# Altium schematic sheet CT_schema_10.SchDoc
size 390 x 385 mm
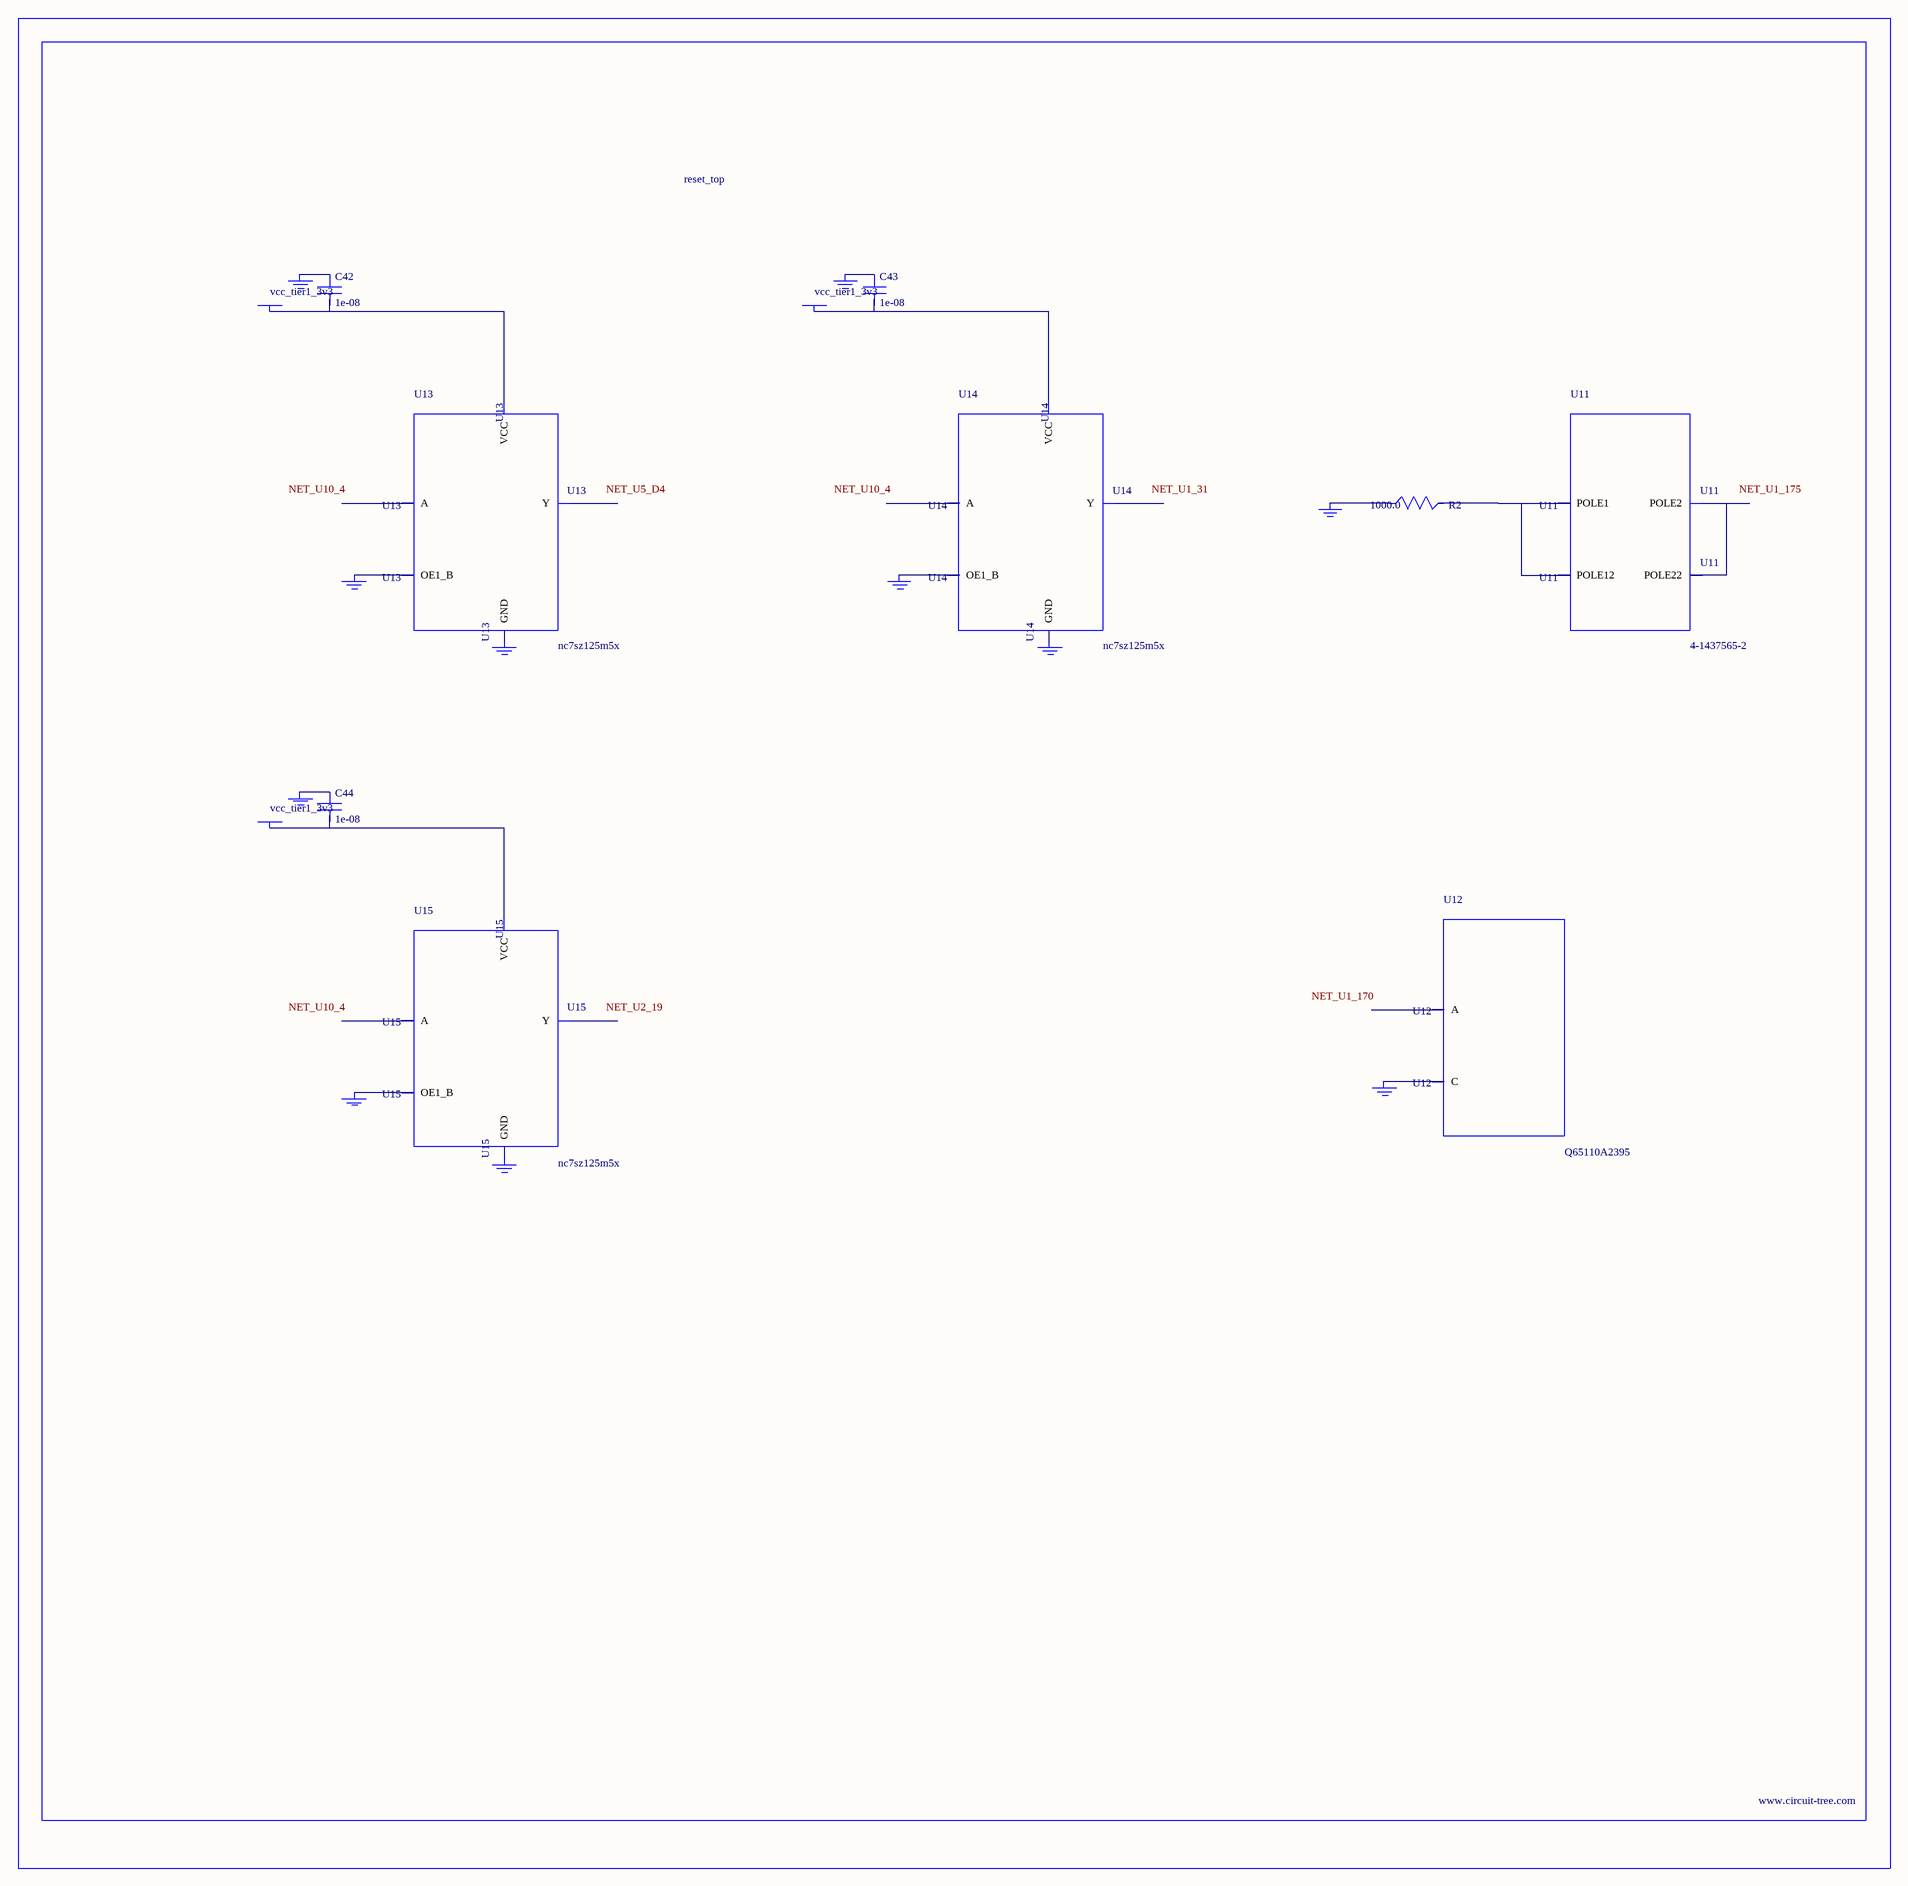
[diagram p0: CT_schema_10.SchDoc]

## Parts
BORDER9  (no value)
C42  1e-08  [C0402]
C43  1e-08  [C0402]
C44  1e-08  [C0402]
GND_INSTANCE_9_0  (no value)
GND_INSTANCE_9_1  (no value)
GND_INSTANCE_9_2  (no value)
GND_INSTANCE_9_3  (no value)
GND_INSTANCE_9_4  (no value)
GND_INSTANCE_9_5  (no value)
GND_INSTANCE_9_6  (no value)
GND_INSTANCE_9_7  (no value)
GND_INSTANCE_9_8  (no value)
GND_INSTANCE_9_9  (no value)
GND_INSTANCE_9_10  (no value)
POWER_INSTANCE_9_0  vcc_tier1_3v3
POWER_INSTANCE_9_1  vcc_tier1_3v3
POWER_INSTANCE_9_2  vcc_tier1_3v3
R2  1000.0  [R0603]
U11  4-1437565-2  [SW_4-1437565-2]
U12  Q65110A2395  [LGM67K-G1J2-24-Z]
U13  nc7sz125m5x  [NC7SZ125M5X]
U14  nc7sz125m5x  [NC7SZ125M5X]
U15  nc7sz125m5x  [NC7SZ125M5X]

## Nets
NetC42_1: C42.1 GND_INSTANCE_9_2.0(GND)
NetC42_2: C42.2 POWER_INSTANCE_9_0.0(PWR) U13.5(VCC)
NetC43_1: C43.1 GND_INSTANCE_9_5.0(GND)
NetC43_2: C43.2 POWER_INSTANCE_9_1.0(PWR) U14.5(VCC)
NetC44_1: C44.1 GND_INSTANCE_9_8.0(GND)
NetC44_2: C44.2 POWER_INSTANCE_9_2.0(PWR) U15.5(VCC)
NetGND_INSTANCE_9_0_0: GND_INSTANCE_9_0.0(GND) R2.1
NetGND_INSTANCE_9_1_0: GND_INSTANCE_9_1.0(GND) U12.C
NetGND_INSTANCE_9_3_0: GND_INSTANCE_9_3.0(GND) U13.1(OE1_B)
NetGND_INSTANCE_9_4_0: GND_INSTANCE_9_4.0(GND) U13.3(GND)
NetGND_INSTANCE_9_6_0: GND_INSTANCE_9_6.0(GND) U14.1(OE1_B)
NetGND_INSTANCE_9_7_0: GND_INSTANCE_9_7.0(GND) U14.3(GND)
NetGND_INSTANCE_9_9_0: GND_INSTANCE_9_9.0(GND) U15.1(OE1_B)
NetGND_INSTANCE_9_10_0: GND_INSTANCE_9_10.0(GND) U15.3(GND)
NetR2_2: R2.2 U11.1(POLE1) U11.2(POLE12)
NetU11_3: U11.3(POLE2) U11.4(POLE22)

Not connected (* = marked no-connect by the designer): U12 A; U13 2(A) 4(Y); U14 2(A) 4(Y); U15 2(A) 4(Y)

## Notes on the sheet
- Labels drawn without touching a wire or pin: NET_U1_31, NET_U1_170, NET_U1_175, NET_U2_19, NET_U5_D4, NET_U10_4

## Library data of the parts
BORDER9 = BORDER_PAGE9
C42-C44 = C0402C103K3RAC
GND_INSTANCE_9_0-GND_INSTANCE_9_10 = GND
POWER_INSTANCE_9_0-POWER_INSTANCE_9_2 = PWR
R2 = RC0603JR-071KL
